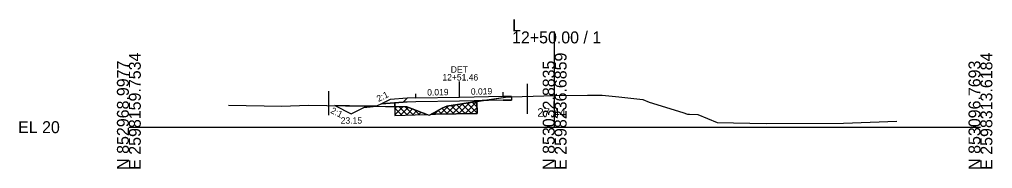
# Model space of a CAD drawing. Extents: x -26 to 1203, y -10 to 9526.
# Drawn here: x -25.7 to 202.8, y 2490.3 to 2525.2 of the extents above; entities that cross this region are included whole.
import ezdxf

# ---------------------------------------------------------------- set-up
doc = ezdxf.new("R2010")
doc.units = 0
for name, color, linetype in [('Exist Cross Section Cell', 7, 'Continuous'), ('Exist XS Center Line Elevation Label', 7, 'Continuous'), ('Exist XS Ground Line', 7, 'Continuous'), ('Prop XS Alignment Label', 7, 'Continuous'), ('Prop XS DDE', 7, 'Continuous'), ('Prop XS DDE Earthwork Shape', 7, 'Continuous'), ('Prop XS DDE Elevations', 7, 'Continuous'), ('Prop XS DDE Slope Text', 7, 'Continuous'), ('Prop XS Earthwork Shape', 7, 'Continuous'), ('Prop XS EOT Tick Mark', 7, 'Continuous'), ('Prop XS Exc Vertical Line 1', 7, 'Continuous'), ('Prop XS Exc Vertical Line 2', 7, 'Continuous'), ('Prop XS Finish Grade', 7, 'Continuous'), ('Prop XS Finish Grade Earthwork', 7, 'Continuous'), ('Prop XS Finish Grade Paved Shoulder', 7, 'Continuous'), ('Prop XS Finish Grade Pavement', 7, 'Continuous'), ('Prop XS Pvmt Edge Slope', 7, 'Continuous'), ('Prop XS SE Text', 7, 'Continuous'), ('Prop XS Side Slope Text', 7, 'Continuous'), ('Prop XS Station Labels', 7, 'Continuous'), ('Prop XS Subgrade Earthwork', 7, 'Continuous'), ('Prop XS Undercut Exc', 7, 'Continuous'), ('Prop XS Undercut Exc Hatch', 7, 'Continuous'), ('Scratch_Level_1', 7, 'Continuous')]:
    doc.layers.add(name, color=color, linetype=linetype)

msp = doc.modelspace()

# ---------------------------------------------------------------- linework, layer by layer
at = {"layer": 'Exist Cross Section Cell'}
for p, q in [((100, 2500), (100, 2522.45)), ((0, 2500), (100, 2500)), ((100, 2500), (200, 2500))]:
    msp.add_line(p, q, dxfattribs=at)
at = {"layer": 'Exist XS Ground Line'}
for p, q in [((81.76, 2506.05), (89.03, 2507.1)), ((89.03, 2507.1), (92.36, 2507.21)), ((92.36, 2507.21), (100.04, 2507.44)), ((100.04, 2507.44), (107.72, 2507.48)), ((107.72, 2507.48), (111.14, 2507.48)), ((111.14, 2507.48), (115.1, 2507.1)), ((115.1, 2507.1), (120.71, 2506.48)), ((23.38, 2505.14), (35.95, 2504.91)), ((35.95, 2504.91), (42.09, 2505.16)), ((42.09, 2505.16), (55.27, 2504.94)), ((55.27, 2504.94), (65.29, 2504.77)), ((65.29, 2504.77), (66.54, 2504.29)), ((73.58, 2504.42), (74.7, 2504.96)), ((74.7, 2504.96), (81.76, 2506.05)), ((120.71, 2506.48), (122.16, 2505.88)), ((122.16, 2505.88), (130.12, 2503.43)), ((66.54, 2504.29), (70.55, 2502.8)), ((70.55, 2502.8), (73.58, 2504.42)), ((130.12, 2503.43), (131.23, 2503.07)), ((131.23, 2503.07), (131.7, 2503.05)), ((131.7, 2503.05), (133.66, 2502.94)), ((133.66, 2502.94), (138.14, 2501.1)), ((138.14, 2501.1), (149.71, 2500.87)), ((149.71, 2500.87), (167.86, 2500.92)), ((167.86, 2500.92), (180.4, 2501.42))]:
    msp.add_line(p, q, dxfattribs=at)
at = {"layer": 'Prop XS DDE'}
for p, q in [((48.38, 2505.05), (52.18, 2503.15)), ((55.16, 2504.64), (58.16, 2504.89)), ((52.18, 2503.15), (55.16, 2504.64))]:
    msp.add_line(p, q, dxfattribs=at)
at = {"layer": 'Prop XS DDE Earthwork Shape'}
for p, q in [((55.27, 2504.94), (48.38, 2505.05)), ((48.38, 2505.05), (52.18, 2503.15)), ((55.16, 2504.64), (58.16, 2504.89)), ((58.16, 2504.89), (55.27, 2504.94)), ((52.18, 2503.15), (55.16, 2504.64))]:
    msp.add_line(p, q, dxfattribs=at)
at = {"layer": 'Prop XS Earthwork Shape'}
for points in [[(89.88, 2507.13), (89.88, 2506.36), (87.88, 2506.32), (82.97, 2506.23), (89.03, 2507.1)], [(59.34, 2505.48), (58.16, 2504.89), (62.43, 2504.82), (62.43, 2505.72), (61.38, 2505.64)], [(64.44, 2505.88), (62.43, 2505.72), (62.43, 2504.82), (65.29, 2504.77), (66.54, 2504.29), (70.01, 2503), (70.55, 2502.8), (70.92, 2503), (73.58, 2504.42), (74.7, 2504.96), (81.76, 2506.05), (81.75, 2506.21), (77.63, 2506.13), (67.38, 2505.94), (65.38, 2505.9)], [(62.43, 2502.72), (69.65, 2503), (70.01, 2503), (66.54, 2504.29), (65.29, 2504.77), (62.43, 2504.82)], [(71.98, 2503.02), (81.8, 2503.21), (81.76, 2506.05), (74.7, 2504.96), (73.58, 2504.42), (70.92, 2503)], [(81.76, 2506.05), (82.97, 2506.23), (81.75, 2506.21)]]:
    msp.add_lwpolyline(points, close=True, dxfattribs=at)
at = {"layer": 'Prop XS EOT Tick Mark'}
for p, q in [((67.38, 2506.85), (67.38, 2507.85)), ((87.88, 2507.24), (87.88, 2508.24))]:
    msp.add_line(p, q, dxfattribs=at)
at = {"layer": 'Prop XS Exc Vertical Line 1'}
msp.add_line((46.9, 2508.42), (46.9, 2502.84), dxfattribs=at)
at = {"layer": 'Prop XS Exc Vertical Line 2'}
msp.add_line((93.51, 2510.19), (93.51, 2503.15), dxfattribs=at)
at = {"layer": 'Prop XS Finish Grade'}
for p, q in [((61.38, 2506.5), (59.34, 2505.48)), ((65.38, 2506.81), (61.38, 2506.5))]:
    msp.add_line(p, q, dxfattribs=at)
at = {"layer": 'Prop XS Finish Grade Earthwork'}
msp.add_line((59.34, 2505.48), (58.16, 2504.89), dxfattribs=at)
at = {"layer": 'Prop XS Finish Grade Paved Shoulder'}
for p, q in [((87.88, 2507.24), (89.88, 2507.28)), ((67.38, 2506.85), (65.38, 2506.81))]:
    msp.add_line(p, q, dxfattribs=at)
at = {"layer": 'Prop XS Finish Grade Pavement'}
for p, q in [((67.38, 2506.85), (77.63, 2507.04)), ((77.63, 2507.04), (87.88, 2507.24))]:
    msp.add_line(p, q, dxfattribs=at)
at = {"layer": 'Prop XS Pvmt Edge Slope'}
msp.add_line((65.38, 2506.81), (64.44, 2505.88), dxfattribs=at)
at = {"layer": 'Prop XS Side Slope Text'}
msp.add_line((77.63, 2507.04), (77.63, 2510.7), dxfattribs=at)
at = {"layer": 'Prop XS Subgrade Earthwork'}
for p, q in [((89.88, 2507.13), (89.88, 2506.36)), ((61.38, 2505.64), (59.34, 2505.48)), ((64.44, 2505.88), (61.38, 2505.64)), ((65.38, 2505.9), (64.44, 2505.88)), ((67.38, 2505.94), (65.38, 2505.9)), ((77.63, 2506.13), (67.38, 2505.94)), ((87.88, 2506.32), (77.63, 2506.13)), ((87.88, 2506.32), (89.88, 2506.36))]:
    msp.add_line(p, q, dxfattribs=at)
at = {"layer": 'Prop XS Undercut Exc'}
for p, q in [((62.43, 2505.72), (62.43, 2502.72)), ((81.8, 2503.21), (81.75, 2506.21)), ((62.43, 2502.72), (69.65, 2503)), ((69.65, 2503), (70.01, 2503)), ((70.92, 2503), (71.98, 2503.02)), ((71.98, 2503.02), (81.8, 2503.21))]:
    msp.add_line(p, q, dxfattribs=at)
at = {"layer": 'Prop XS Undercut Exc Hatch'}
for p, q in [((65.29, 2504.77), (62.43, 2504.82)), ((62.43, 2504.31), (62.93, 2504.81)), ((62.43, 2502.9), (64.32, 2504.79)), ((63.49, 2504.8), (65.45, 2502.84)), ((64.92, 2504.78), (66.81, 2502.89)), ((70.01, 2503), (65.29, 2504.77)), ((73.12, 2503.04), (75.09, 2505.01)), ((74.55, 2504.88), (76.32, 2503.1)), ((74.56, 2503.07), (76.76, 2505.28)), ((75.72, 2505.11), (77.71, 2503.13)), ((76, 2503.1), (78.44, 2505.54)), ((76.95, 2505.3), (79.1, 2503.16)), ((77.44, 2503.12), (80.11, 2505.8)), ((78.17, 2505.49), (80.48, 2503.18)), ((78.88, 2503.15), (81.75, 2506.02)), ((79.39, 2505.68), (81.8, 2503.28)), ((80.62, 2505.88), (81.78, 2504.72)), ((62.43, 2504.44), (64.09, 2502.79)), ((62.43, 2503.03), (62.73, 2502.73)), ((63.72, 2502.77), (65.6, 2504.65)), ((65.19, 2502.83), (66.63, 2504.27)), ((66.66, 2502.89), (67.66, 2503.88)), ((66.98, 2504.14), (68.17, 2502.94)), ((68.13, 2502.94), (68.68, 2503.5)), ((69.24, 2503.29), (69.53, 2503)), ((69.6, 2503), (69.71, 2503.11)), ((70, 2503), (70, 2503)), ((71.68, 2503.02), (72.45, 2503.79)), ((71.75, 2503.43), (72.15, 2503.03)), ((72.68, 2503.91), (73.54, 2503.05)), ((73.61, 2504.39), (74.93, 2503.08)), ((80.32, 2503.18), (81.78, 2504.63)), ((81.77, 2503.21), (81.8, 2503.24))]:
    msp.add_line(p, q, dxfattribs=at)
msp.add_lwpolyline([(71.98, 2503.02), (70.92, 2503), (73.58, 2504.42), (74.7, 2504.96), (81.75, 2506.05), (81.8, 2503.21)], close=True, dxfattribs=at)
at = {"layer": 'Scratch_Level_1'}
msp.add_lwpolyline([(61.38, 2506.5), (59.34, 2505.48), (61.38, 2505.64), (64.44, 2505.88), (65.38, 2506.81)], close=True, dxfattribs=at)

# ---------------------------------------------------------------- texts
at = {"layer": 'Exist Cross Section Cell'}
for s, p in [('L', (90, 2522.45)), ('12+50.00 / 1', (90, 2519.65)), ('EL 20', (-26, 2498.6))]:
    msp.add_text(s, height=2.8, dxfattribs=at).set_placement(p)
for s, p in [('E 2598159.7534', (2.8, 2490)), ('E 2598236.6859', (102.8, 2490)), ('E 2598313.6184', (202.8, 2490)), ('N 852968.9977', (0, 2490)), ('N 853032.8835', (100, 2490)), ('N 853096.7693', (200, 2490))]:
    msp.add_text(s, height=2.8, rotation=90, dxfattribs=at).set_placement(p)
at = {"layer": 'Exist XS Center Line Elevation Label'}
msp.add_text('27.44', height=2, dxfattribs=at).set_placement((95.93, 2502.44))
at = {"layer": 'Prop XS Alignment Label'}
msp.add_text('DET', height=1.5, dxfattribs=at).set_placement((75.6, 2512.79))
at = {"layer": 'Prop XS DDE Elevations'}
msp.add_text('23.15', height=1.5, rotation=360, dxfattribs=at).set_placement((49.75, 2500.83))
at = {"layer": 'Prop XS DDE Slope Text'}
msp.add_text('2:1', height=1.5, rotation=333.4349, dxfattribs=at).set_placement((47.23, 2503.41))
at = {"layer": 'Prop XS SE Text'}
for rotation, p in [(1.0767, (70.08, 2507.4)), (1.0783, (80.33, 2507.6))]:
    msp.add_text('0.019', height=1.5, rotation=rotation, dxfattribs=at).set_placement(p)
at = {"layer": 'Prop XS Side Slope Text'}
msp.add_text('2:1', height=1.5, rotation=26.5651, dxfattribs=at).set_placement((58.65, 2505.89))
at = {"layer": 'Prop XS Station Labels'}
msp.add_text('12+51.46', height=1.5, dxfattribs=at).set_placement((73.63, 2510.94))

doc.saveas('drawing.dxf')
